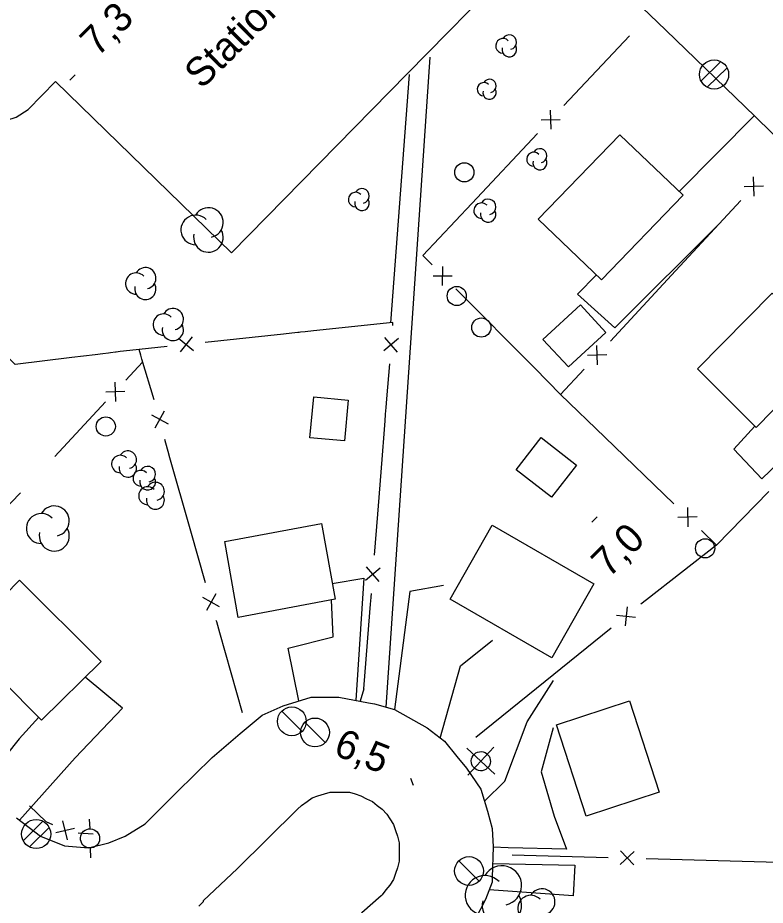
# Model space of a CAD drawing. Extents: x 381879 to 384696, y 5564785 to 5567594.
# Drawn here: x 383086.9 to 383164.9, y 5565288.9 to 5565381.4 of the extents above; entities that cross this region are included whole.
import ezdxf

# ---------------------------------------------------------------- set-up
doc = ezdxf.new("R2010")
doc.units = 0
for name, color, linetype in [('Niveau 19', 7, 'Continuous'), ('Niveau 21', 7, 'Continuous'), ('Niveau 22', 7, 'Continuous'), ('Niveau 3', 7, 'Continuous'), ('Niveau 31', 7, 'Continuous'), ('Niveau 36', 7, 'Continuous'), ('Niveau 37', 7, 'Continuous'), ('Niveau 44', 7, 'Continuous'), ('Niveau 52', 7, 'Continuous')]:
    doc.layers.add(name, color=color, linetype=linetype)

msp = doc.modelspace()

# ---------------------------------------------------------------- linework, layer by layer
at = {"layer": 'Niveau 19'}
for points in [[(383163.72, 5565371.18), (383155.89, 5565363.29)], [(383147.28, 5565354.6), (383145.29, 5565352.6), (383149.17, 5565349.08), (383160.24, 5565360.11)], [(383163.77, 5565338.83), (383161.59, 5565336.42), (383164.5, 5565333.35), (383183.6, 5565351.69)], [(383119.71, 5565322.43), (383123.02, 5565323), (383122.16, 5565310.26)], [(383131.32, 5565322.23), (383127.79, 5565321.59), (383126.2, 5565309.3)], [(383116.24, 5565310.21), (383115.13, 5565315.69), (383119.8, 5565316.89), (383119.62, 5565320.73)], [(383130.98, 5565306.33), (383133.1, 5565313.85), (383136.43, 5565316.53)], [(383087.09, 5565297.78), (383092.92, 5565304.28), (383097.84, 5565309.43), (383093.94, 5565312.67)], [(383135.58, 5565299.74), (383137.7, 5565301.84), (383140.02, 5565308.02), (383142.8, 5565312.34)], [(383123, 5565311.44), (383122.63, 5565310.17)], [(383089.1, 5565308.5), (383087.06, 5565306.26), (383083.23, 5565301.48)], [(383142.74, 5565307.39), (383141.49, 5565302.82), (383142.84, 5565298.19), (383144.15, 5565294.73), (383138.06, 5565294.88), (383136.5, 5565294.96)], [(383136.45, 5565293.25), (383136.45, 5565293.25), (383145.01, 5565293.07), (383144.82, 5565289.9), (383136.09, 5565290.5)]]:
    msp.add_lwpolyline(points, dxfattribs=at)
at = {"layer": 'Niveau 21'}
for points in [[(383163.8, 5565371.1), (383154.5, 5565380.1), (383141.3, 5565392.8), (383129.4, 5565404.5), (383122.85, 5565410.57), (383116.3, 5565417.4), (383102.1, 5565431.1), (383087.97, 5565444.43)], [(383167.3, 5565367.7), (383163.8, 5565371.1)], [(383086.8, 5565298), (383089.3, 5565296.1), (383091.8, 5565295.1), (383094.3, 5565294.9), (383096.4, 5565295.4), (383098.1, 5565296.1), (383100.2, 5565297.4), (383103.5, 5565300.7), (383107.2, 5565304.3), (383110.1, 5565306.8), (383112.4, 5565308.7), (383114.6, 5565309.7), (383117.5, 5565310.6), (383120.4, 5565310.6), (383123.5, 5565310), (383124.1, 5565309.9)], [(383124.1, 5565309.9), (383126.2, 5565309.3)], [(383126.2, 5565309.3), (383129.6, 5565307.4), (383131.4, 5565306), (383132.7, 5565304.4)], [(383132.7, 5565304.4), (383133.7, 5565303.2), (383135.2, 5565301), (383135.9, 5565298.7)], [(383116.1, 5565298.9), (383116.5, 5565299.3), (383117.1, 5565299.7), (383117.6, 5565300.1), (383118.2, 5565300.3), (383118.9, 5565300.5), (383119.5, 5565300.7), (383120.2, 5565300.7), (383120.8, 5565300.7), (383121.5, 5565300.7), (383122.1, 5565300.5), (383122.7, 5565300.3), (383123.3, 5565300), (383123.9, 5565299.7), (383124.4, 5565299.3), (383124.9, 5565298.9), (383125.4, 5565298.4), (383125.7, 5565297.9), (383126.1, 5565297.3), (383126.3, 5565296.7), (383126.5, 5565296.1), (383126.7, 5565295.4), (383126.7, 5565294.8), (383126.7, 5565294.1), (383126.7, 5565293.5), (383126.5, 5565292.8), (383126.3, 5565292.2), (383126.1, 5565291.6), (383125.7, 5565291), (383125.3, 5565290.5), (383124.9, 5565290), (383124.8, 5565289.9)], [(383106.3, 5565289.4), (383109.8, 5565292.7), (383116.1, 5565298.9)], [(383135.9, 5565298.7), (383136.4, 5565296.9), (383136.5, 5565295), (383136.4, 5565291.8)], [(383136.4, 5565291.8), (383136.4, 5565291.3), (383135.7, 5565289.5), (383133.52, 5565285.32), (383127.82, 5565279.62)], [(383105.8, 5565288.8), (383106.3, 5565289.3), (383106.3, 5565289.4)], [(383124.8, 5565289.9), (383122.8, 5565288.1), (383120.2, 5565285.5)]]:
    msp.add_lwpolyline(points, dxfattribs=at)
at = {"layer": 'Niveau 22'}
for points in [[(383129.9, 5565377.3), (383125.31, 5565309.55)], [(383125.81, 5565349.6), (383127.76, 5565375.48)]]:
    msp.add_lwpolyline(points, dxfattribs=at)
at = {"layer": 'Niveau 3'}
for p, q in [((383092.34, 5565374.88), (383092.91, 5565375.45)), ((383146.78, 5565328.83), (383147.35, 5565329.4)), ((383127.87, 5565302.16), (383128.15, 5565301.41))]:
    msp.add_line(p, q, dxfattribs=at)
at = {"layer": 'Niveau 31'}
for points in [[(383147.8, 5565354.1), (383156.3, 5565362.9), (383149.7, 5565369.2), (383141.2, 5565360.4)], [(383163.9, 5565338.7), (383170.9, 5565345.8), (383169.4, 5565347.3), (383170.2, 5565348.1), (383165.6, 5565352.7), (383157.8, 5565344.8)], [(383148.25, 5565348.61), (383144.33, 5565345), (383141.68, 5565347.88), (383145.6, 5565351.49)], [(383121.37, 5565341.55), (383120.98, 5565337.3), (383117.39, 5565337.63), (383117.78, 5565341.88)], [(383138.89, 5565334.28), (383141.49, 5565337.64), (383145.18, 5565334.78), (383142.58, 5565331.42)], [(383109.9, 5565318.9), (383108.5, 5565326.8), (383118.6, 5565328.7), (383120, 5565320.8)], [(383132, 5565320.8), (383136.4, 5565328.5), (383147, 5565322.4), (383142.6, 5565314.7)], [(383081, 5565316.6), (383087.1, 5565322.8), (383095.6, 5565314.3), (383089.4, 5565308.2)], [(383143.1, 5565307.7), (383150.7, 5565310.2), (383153.8, 5565300.7), (383146.2, 5565298.2)]]:
    msp.add_lwpolyline(points, close=True, dxfattribs=at)
at = {"layer": 'Niveau 36'}
for p, q in [((383160.22, 5565376.83), (383158.16, 5565374.79)), ((383158.82, 5565374.15), (383160.88, 5565376.19)), ((383116.57, 5565307), (383114.45, 5565309.12)), ((383118.98, 5565305.85), (383116.86, 5565307.97)), ((383133.74, 5565305.28), (383136.65, 5565302.56)), ((383133.84, 5565302.47), (383136.56, 5565305.38)), ((383089.53, 5565297.66), (383087.47, 5565295.62)), ((383094.38, 5565297.86), (383094.43, 5565296.86)), ((383088.13, 5565294.98), (383090.19, 5565297.02)), ((383094.53, 5565293.86), (383094.49, 5565294.86)), ((383135.04, 5565291.41), (383132.92, 5565293.53))]:
    msp.add_line(p, q, dxfattribs=at)
for centre, radius in [((383159.528, 5565375.492), 1.518), ((383133.483, 5565365.29), 1), ((383132.693, 5565352.4), 1), ((383135.253, 5565349.11), 1), ((383096.093, 5565338.8), 1), ((383158.593, 5565326.1), 1), ((383115.502, 5565308.065), 1.5), ((383117.912, 5565306.915), 1.5), ((383088.838, 5565296.322), 1.518), ((383133.972, 5565292.475), 1.5)]:
    msp.add_circle(centre, radius, dxfattribs=at)
for centre, major_axis, ratio in [((383135.207, 5565303.916), (-0.048, -0.999), 0.999982), ((383094.459, 5565295.871), (-0.05, -0.999), 0.999983)]:
    msp.add_ellipse(centre, major_axis=major_axis, ratio=ratio, dxfattribs=at)
at = {"layer": 'Niveau 37'}
for p, q in [((383142.45, 5565371.78), (383142.51, 5565369.78)), ((383141.48, 5565370.75), (383143.49, 5565370.81)), ((383163.72, 5565362.81), (383163.65, 5565364.81)), ((383164.68, 5565363.85), (383162.68, 5565363.78)), ((383131.22, 5565353.49), (383131.23, 5565355.49)), ((383130.22, 5565354.49), (383132.22, 5565354.49)), ((383103.69, 5565347.99), (383105.25, 5565346.73)), ((383105.1, 5565348.14), (383103.84, 5565346.58)), ((383126.62, 5565347.98), (383125.1, 5565346.68)), ((383126.51, 5565346.56), (383125.21, 5565348.09)), ((383147.38, 5565345.23), (383147.31, 5565347.23)), ((383148.35, 5565346.27), (383146.34, 5565346.2)), ((383097.13, 5565341.42), (383097.06, 5565343.43)), ((383098.09, 5565342.46), (383096.09, 5565342.39)), ((383101.24, 5565338.67), (383102.21, 5565340.42)), ((383100.85, 5565340.03), (383102.6, 5565339.06)), ((383156.75, 5565330.35), (383156.78, 5565328.35)), ((383157.77, 5565329.37), (383155.76, 5565329.33)), ((383124.72, 5565324.05), (383123.19, 5565322.75)), ((383124.6, 5565322.64), (383123.3, 5565324.16)), ((383107.95, 5565320), (383106.2, 5565320.98)), ((383107.56, 5565321.37), (383106.59, 5565319.62)), ((383150.45, 5565320.02), (383150.24, 5565318.03)), ((383149.35, 5565319.13), (383151.34, 5565318.92)), ((383092.09, 5565295.73), (383091.63, 5565297.69)), ((383090.89, 5565296.48), (383092.84, 5565296.93)), ((383149.74, 5565293.14), (383151.19, 5565294.52)), ((383151.15, 5565293.1), (383149.78, 5565294.56))]:
    msp.add_line(p, q, dxfattribs=at)
for points in [[(383150.71, 5565379.52), (383143.86, 5565372.24)], [(383141.11, 5565369.33), (383134.26, 5565362.05)], [(383155.51, 5565355.02), (383162.32, 5565362.35)], [(383134.26, 5565362.05), (383129.16, 5565356.63), (383130.12, 5565355.66)], [(383148.71, 5565347.7), (383155.51, 5565355.02)], [(383132.6, 5565353.16), (383140.82, 5565344.87)], [(383126.02, 5565349.32), (383126.04, 5565349.63), (383117.76, 5565348.76), (383116.89, 5565348.67), (383116.4, 5565348.62)], [(383116.4, 5565348.62), (383116.25, 5565348.6), (383116.13, 5565348.59), (383116.12, 5565348.59), (383115.51, 5565348.52), (383115.48, 5565348.52), (383114.63, 5565348.43), (383106.47, 5565347.57), (383106.46, 5565347.57)], [(383092.55, 5565345.98), (383086.65, 5565345.25), (383083.76, 5565348.1)], [(383102.48, 5565347.15), (383099.56, 5565346.84), (383097.95, 5565346.64), (383097.59, 5565346.6), (383097.19, 5565346.55), (383097.18, 5565346.55), (383097.12, 5565346.54), (383096.6, 5565346.47), (383096.59, 5565346.47), (383096.37, 5565346.45), (383095.78, 5565346.37), (383094.98, 5565346.28), (383092.55, 5565345.98)], [(383101.15, 5565341.58), (383099.85, 5565345.81), (383099.74, 5565346.22), (383099.56, 5565346.84)], [(383098.19, 5565343.64), (383099.94, 5565345.52)], [(383124.9, 5565335.36), (383125.15, 5565338.49), (383125.22, 5565339.38), (383125.28, 5565340.05), (383125.28, 5565340.08), (383125.34, 5565340.78), (383125.41, 5565341.67), (383125.7, 5565345.33)], [(383140.82, 5565344.87), (383143.53, 5565342.13), (383143.54, 5565342.12), (383143.56, 5565342.1)], [(383148.13, 5565337.69), (383143.53, 5565342.13), (383145.98, 5565344.77)], [(383090.78, 5565335.67), (383096.08, 5565341.37)], [(383106.5, 5565322.52), (383104.96, 5565327.9), (383102.71, 5565335.79), (383102.71, 5565335.8), (383102.24, 5565337.43)], [(383155.33, 5565330.74), (383148.13, 5565337.69)], [(383124.11, 5565325.4), (383124.45, 5565329.67), (383124.52, 5565330.54), (383124.9, 5565335.36)], [(383087.19, 5565331.87), (383080.23, 5565324.69)], [(383165.23, 5565332.01), (383159.79, 5565326.43), (383158.2, 5565327.96)], [(383159.79, 5565326.43), (383152.48, 5565320.75), (383151.9, 5565320.28)], [(383123, 5565311.44), (383123.63, 5565319.4), (383123.7, 5565320.29), (383123.76, 5565320.99), (383123.76, 5565321.02), (383123.79, 5565321.41)], [(383110.36, 5565308.95), (383107.98, 5565317.31), (383107.66, 5565318.43), (383107.62, 5565318.57)], [(383148.79, 5565317.77), (383141.01, 5565311.49)], [(383141.01, 5565311.49), (383134.69, 5565306.39)], [(383088.14, 5565299.25), (383089.83, 5565297.64), (383090.54, 5565297.31)], [(383093.21, 5565296.45), (383094.79, 5565296.35)], [(383138.47, 5565294.16), (383148.47, 5565293.89)], [(383152.46, 5565293.78), (383162.46, 5565293.5)], [(383162.46, 5565293.5), (383172.46, 5565293.23)]]:
    msp.add_lwpolyline(points, dxfattribs=at)
at = {"layer": 'Niveau 44'}
for centre, radius, start, end in [((383137.523, 5565378.472), 0.761, 44.11535, 269.80394), ((383138.177, 5565378.853), 0.761, 282.26915, 149.72624), ((383138.177, 5565378.091), 0.761, 166.93684, 29.62121), ((383135.515, 5565373.949), 0.694, 44.11535, 269.80394), ((383136.112, 5565374.296), 0.694, 282.26915, 149.72624), ((383136.112, 5565373.602), 0.694, 166.93684, 29.62121), ((383140.729, 5565366.651), 0.734, 44.11535, 269.80394), ((383141.361, 5565367.018), 0.734, 282.26915, 149.72624), ((383141.361, 5565366.284), 0.734, 166.93684, 29.62121), ((383122.153, 5565362.452), 0.761, 44.11535, 269.80394), ((383122.807, 5565362.833), 0.761, 282.26915, 149.72624), ((383122.807, 5565362.071), 0.761, 166.93684, 29.62121), ((383135.968, 5565361.698), 0.808, 282.26915, 149.72624), ((383106.8, 5565360.058), 1.546, 282.26915, 149.72624), ((383135.273, 5565361.294), 0.808, 44.11535, 269.80394), ((383105.471, 5565359.285), 1.546, 44.11535, 269.80394), ((383135.968, 5565360.89), 0.808, 166.93684, 29.62121), ((383106.8, 5565358.512), 1.546, 166.93684, 29.62121), ((383100.218, 5565354.252), 1.11, 282.26915, 149.72624), ((383099.264, 5565353.697), 1.11, 44.11535, 269.80394), ((383100.218, 5565353.142), 1.11, 166.93684, 29.62121), ((383102.134, 5565349.427), 1.11, 44.11535, 269.80394), ((383103.088, 5565349.982), 1.11, 282.26915, 149.72624), ((383103.088, 5565348.872), 1.11, 166.93684, 29.62121), ((383097.61, 5565334.888), 0.909, 44.11535, 269.80394), ((383098.392, 5565335.342), 0.909, 282.26915, 149.72624), ((383098.392, 5565334.434), 0.909, 166.93684, 29.62121), ((383100.461, 5565333.825), 0.821, 282.26915, 149.72624), ((383099.755, 5565333.415), 0.821, 44.11535, 269.80394), ((383100.461, 5565333.004), 0.821, 166.93684, 29.62121), ((383101.268, 5565332.047), 0.935, 282.26915, 149.72624), ((383100.463, 5565331.579), 0.935, 44.11535, 269.80394), ((383101.268, 5565331.112), 0.935, 166.93684, 29.62121), ((383090.725, 5565328.949), 1.566, 282.26915, 149.72624), ((383089.378, 5565328.166), 1.566, 44.11535, 269.80394), ((383090.725, 5565327.383), 1.566, 166.93684, 29.62121), ((383137.399, 5565290.964), 2.055, 282.26915, 149.72624), ((383135.631, 5565289.936), 2.055, 44.11535, 269.80394), ((383141.576, 5565289.256), 1.358, 282.26915, 149.72624), ((383137.399, 5565288.909), 2.055, 166.93684, 29.62121), ((383140.408, 5565288.577), 1.358, 44.11535, 269.80394)]:
    msp.add_arc(centre, radius, start, end, dxfattribs=at)
at = {"layer": 'Niveau 52'}
msp.add_lwpolyline([(383035.85, 5565407.02), (383053.65, 5565389.72), (383069.09, 5565374.65), (383072.03, 5565371.98), (383074.04, 5565370.66), (383075.68, 5565369.9), (383077.84, 5565369.58), (383079.81, 5565369.53), (383082.77, 5565369.84), (383084.78, 5565370.4), (383086.76, 5565371.04), (383088, 5565371.83), (383090.86, 5565374.74), (383109.19, 5565356.9), (383127.51, 5565375.57), (383138.19, 5565386.44), (383135.18, 5565389.09), (383134.99, 5565389.62), (383134.88, 5565389.92), (383135.05, 5565390.15), (383139.44, 5565394.63)], dxfattribs=at)

# ---------------------------------------------------------------- texts
at = {"layer": 'Niveau 3'}
for s, rotation, p in [('7,3  ', 44.7717, (383095.23, 5565377.25)), ('7,0', 44.7717, (383148.54, 5565322.94)), ('6,5  ', 338.32008, (383119.72, 5565304.63))]:
    msp.add_text(s, height=3, rotation=rotation, dxfattribs=at).set_placement(p)
at = {"layer": 'Niveau 52'}
msp.add_text('Stationnement', height=3, rotation=44.7717, dxfattribs=at).set_placement((383106.1, 5565373.87))

doc.saveas('drawing.dxf')
